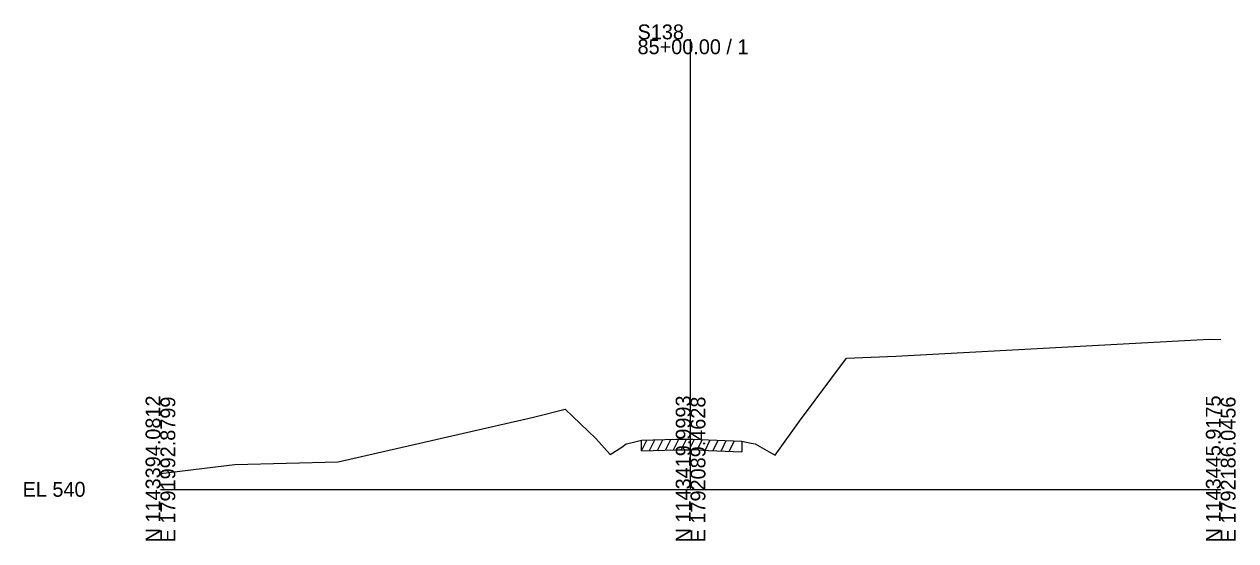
# Model space of a CAD drawing. Extents: x -26 to 1203, y -10 to 19606.
# Drawn here: x -25.7 to 202.8, y 9990.3 to 10087.7 of the extents above; entities that cross this region are included whole.
import ezdxf

# ---------------------------------------------------------------- set-up
doc = ezdxf.new("R2010")
doc.units = 0
for name, color, linetype in [('RD_EX_Driveway', 7, 'Continuous'), ('RD_GPK_XS_Cell', 7, 'Continuous'), ('RD_XS_ExGround', 7, 'Continuous'), ('RD_XS_ExPaveRet', 7, 'Continuous')]:
    doc.layers.add(name, color=color, linetype=linetype)

msp = doc.modelspace()

# ---------------------------------------------------------------- linework, layer by layer
at = {"layer": 'RD_GPK_XS_Cell'}
for p, q in [((100, 10000), (100, 10084.83)), ((0, 10000), (100, 10000)), ((100, 10000), (200, 10000))]:
    msp.add_line(p, q, dxfattribs=at)
at = {"layer": 'RD_XS_ExGround'}
msp.add_lwpolyline([(0, 10002.98), (14.02, 10004.69), (33.51, 10005.17), (70.4, 10013.62), (76.32, 10015.11), (82.11, 10009.6), (84.85, 10006.57), (87.01, 10007.97), (87.84, 10008.56), (88.74, 10008.77), (90.75, 10009.26), (97.36, 10009.43), (100, 10009.47), (100.4, 10009.48), (103.35, 10009.32), (109.66, 10009.05), (111.43, 10008.73), (112.17, 10008.6), (114.82, 10007.08), (115.96, 10006.41), (120.55, 10012.86), (129.44, 10024.73), (138.69, 10025.11), (197.82, 10028.28), (200, 10028.27)], dxfattribs=at)
at = {"layer": 'RD_XS_ExPaveRet'}
for p, q in [((90.75, 10007.26), (91.76, 10009.28)), ((90.75, 10007.26), (90.75, 10009.26)), ((92.25, 10007.3), (93.26, 10009.32)), ((93.75, 10007.34), (94.76, 10009.36)), ((95.25, 10007.38), (96.26, 10009.4)), ((96.75, 10007.42), (97.76, 10009.44)), ((97.36, 10007.43), (100, 10007.47)), ((98.25, 10007.45), (99.25, 10009.46)), ((99.75, 10007.47), (100.74, 10009.46)), ((100, 10007.47), (100.4, 10007.48)), ((100.4, 10007.48), (103.35, 10007.32)), ((101.25, 10007.43), (102.22, 10009.38)), ((102.75, 10007.35), (103.72, 10009.31)), ((104.25, 10007.29), (105.22, 10009.24)), ((105.75, 10007.22), (106.72, 10009.18)), ((107.25, 10007.16), (108.22, 10009.11)), ((109.66, 10009.05), (109.66, 10007.05)), ((90.75, 10007.26), (97.36, 10007.43)), ((103.35, 10007.32), (109.66, 10007.05))]:
    msp.add_line(p, q, dxfattribs=at)

# ---------------------------------------------------------------- texts
at = {"layer": 'RD_EX_Driveway'}
msp.add_text('544.74', height=0.0975, rotation=90, dxfattribs=at).set_placement((100.1, 10009.47))
at = {"layer": 'RD_GPK_XS_Cell'}
for s, p in [('S138', (90, 10084.83)), ('85+00.00 / 1', (90, 10082.03)), ('EL 540', (-26, 9998.6))]:
    msp.add_text(s, height=2.8, dxfattribs=at).set_placement(p)
for s, p in [('N 1143394.0812', (0, 9990)), ('E 1791992.8799', (2.8, 9990)), ('N 1143419.9993', (100, 9990)), ('E 1792089.4628', (102.8, 9990)), ('N 1143445.9175', (200, 9990)), ('E 1792186.0456', (202.8, 9990))]:
    msp.add_text(s, height=2.8, rotation=90, dxfattribs=at).set_placement(p)

doc.saveas('drawing.dxf')
